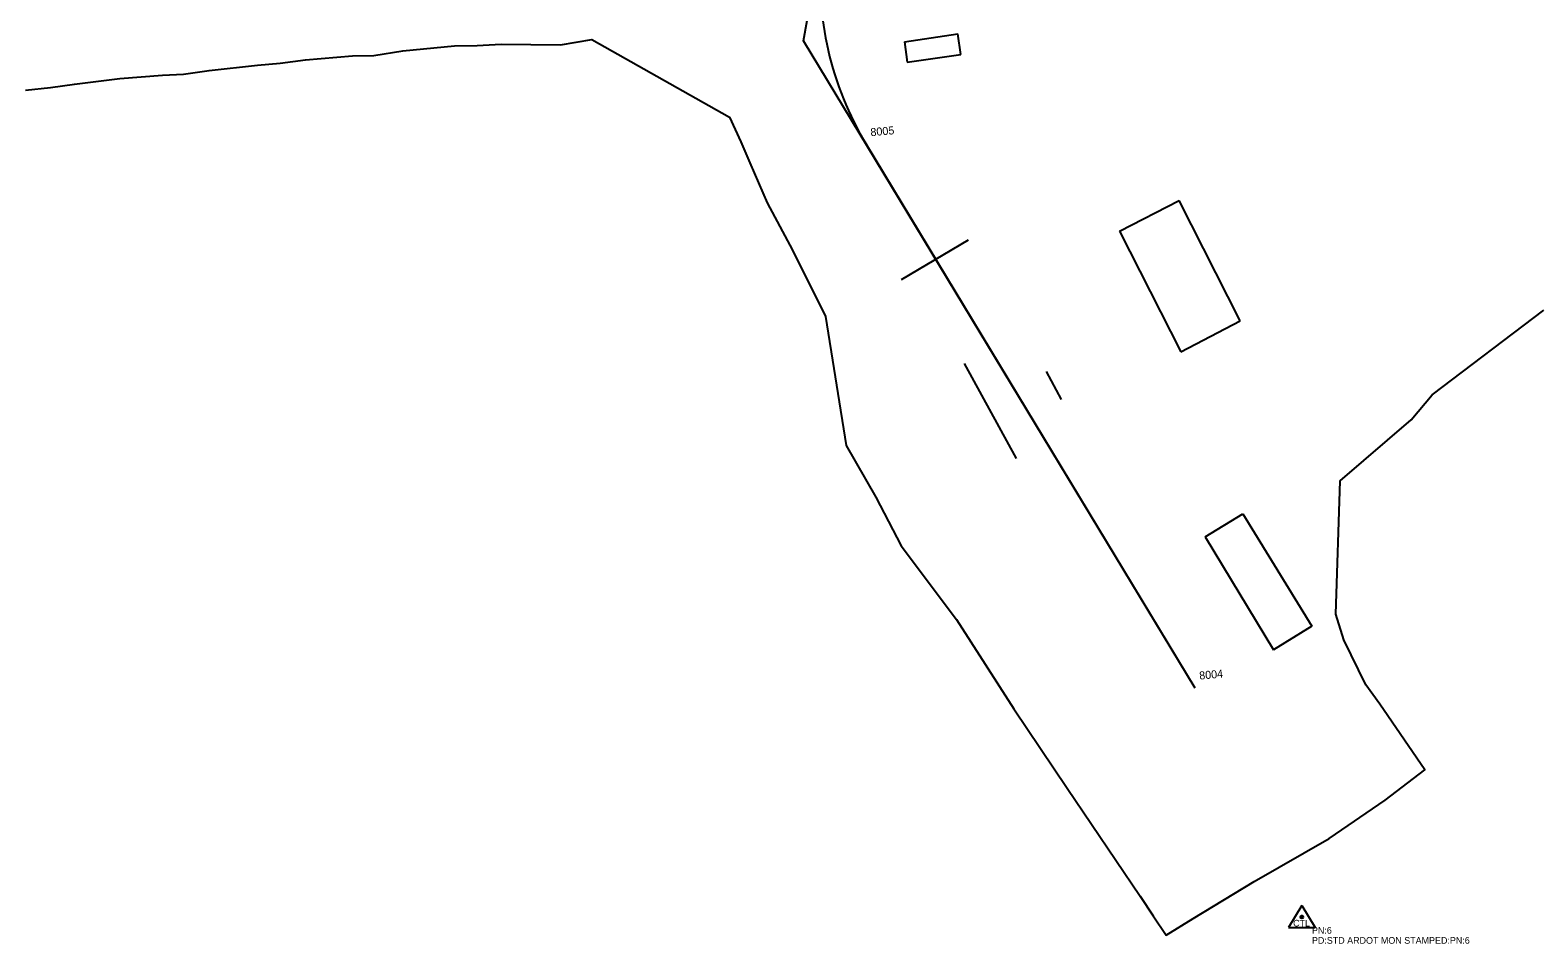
# Model space of a CAD drawing. Extents: x 1734463 to 1738841, y 377458 to 380217.
# Drawn here: x 1735592 to 1736720, y 377458 to 378142 of the extents above; entities that cross this region are included whole.
import ezdxf

# ---------------------------------------------------------------- set-up
doc = ezdxf.new("R2010")
doc.units = 0
doc.layers.add('R_Horz Alg Stationing', color=7, linetype='Continuous')
doc.layers.add('S_PRIMARY_CTL_ANNOT', color=7, linetype='Continuous')

msp = doc.modelspace()

# ---------------------------------------------------------------- linework, layer by layer
for p, q in [((1736170.6, 378134.3), (1736210.9, 378361.2)), ((1736463.7, 377649.8), (1736170.6, 378134.3)), ((1736246.2, 378133.5), (1736286.1, 378139.4)), ((1736246.2, 378133.5), (1736286.1, 378139.4)), ((1736246.2, 378133.5), (1736248.3, 378118.3)), ((1736246.2, 378133.5), (1736248.3, 378118.3)), ((1736288.3, 378124), (1736286.1, 378139.4)), ((1736288.3, 378124), (1736286.1, 378139.4)), ((1736248.3, 378118.3), (1736288.3, 378124)), ((1736248.3, 378118.3), (1736288.3, 378124)), ((1736463.7, 377649.8), (1736217.7, 378056.5)), ((1736407.1, 377991.8), (1736451.9, 378014.7)), ((1736407.1, 377991.8), (1736451.9, 378014.7)), ((1736497.6, 377924.7), (1736451.9, 378014.7)), ((1736497.6, 377924.7), (1736451.9, 378014.7)), ((1736407.1, 377991.8), (1736453, 377901.5)), ((1736407.1, 377991.8), (1736453, 377901.5)), ((1736243.9, 377955.6), (1736294.1, 377985.3)), ((1736243.9, 377955.6), (1736294.1, 377985.3)), ((1736453, 377901.5), (1736497.6, 377924.7)), ((1736453, 377901.5), (1736497.6, 377924.7)), ((1736291, 377892.8), (1736329.8, 377821.7)), ((1736291, 377892.8), (1736329.8, 377821.7)), ((1736363.8, 377865.7), (1736352.6, 377886.7)), ((1736363.8, 377865.7), (1736352.6, 377886.7)), ((1736471.2, 377762.9), (1736499.4, 377780.2)), ((1736471.2, 377762.9), (1736499.4, 377780.2)), ((1736499.4, 377780.2), (1736551.2, 377696.1)), ((1736499.4, 377780.2), (1736551.2, 377696.1)), ((1736471.2, 377762.9), (1736522.5, 377678.3)), ((1736471.2, 377762.9), (1736522.5, 377678.3)), ((1736551.2, 377696.1), (1736522.5, 377678.3)), ((1736551.2, 377696.1), (1736522.5, 377678.3))]:
    msp.add_line(p, q)
msp.add_lwpolyline([(1735588.3, 378097.3), (1735607, 378099.4), (1735624.8, 378101.8), (1735658.8, 378105.9), (1735690.8, 378108.4), (1735706.6, 378109.2), (1735725.8, 378111.9), (1735762, 378116), (1735778.8, 378117.5), (1735797.9, 378120), (1735833, 378122.9), (1735849, 378123.2), (1735870.7, 378126.7), (1735909.4, 378130.4), (1735926.3, 378130.6), (1735944.2, 378131.7), (1735988.6, 378131.2), (1736012.1, 378135.2), (1736115.2, 378077.1), (1736123.6, 378058.5), (1736130.4, 378042.9), (1736136.9, 378027.9), (1736143.4, 378012.9), (1736152.9, 377995.3), (1736162.4, 377977.6), (1736187, 377927.9), (1736202.6, 377831.4), (1736224.7, 377792.6), (1736234.2, 377774.5), (1736243.6, 377756.3), (1736285.1, 377701.2), (1736328.1, 377634.3), (1736367.9, 377574.9), (1736422.5, 377494), (1736432.3, 377479.4), (1736442.2, 377464.9), (1736462.2, 377477.3), (1736507.9, 377505), (1736564, 377537.2), (1736606.1, 377565.8), (1736635.6, 377588.5), (1736602, 377637.8), (1736591.6, 377652.2), (1736575.2, 377685.9), (1736569, 377705.2), (1736572.3, 377805), (1736625.5, 377850.6), (1736641.3, 377869.2), (1736724.7, 377932.5)])
msp.add_arc((1736424.1, 378181.4), 241.2, 174.7889, 211.1667)
at = {"layer": 'S_PRIMARY_CTL_ANNOT'}
for p, q in [((1736543.7, 377487.1), (1736533.7, 377470.6)), ((1736543.7, 377487.1), (1736553.5, 377470.6)), ((1736533.7, 377470.6), (1736553.5, 377470.6))]:
    msp.add_line(p, q, dxfattribs=at)
for radius in [1.04, 0.609, 0.344]:
    msp.add_circle((1736543.7, 377478.4), radius, dxfattribs=at)

# ---------------------------------------------------------------- texts
at = {"layer": 'R_Horz Alg Stationing'}
for s, p in [('8005', (1736221, 378062.8)), ('8004', (1736467.1, 377656.1))]:
    msp.add_text(s, height=6, rotation=5, dxfattribs=at).set_placement(p)
at = {"layer": 'S_PRIMARY_CTL_ANNOT'}
for s, p in [('CTL', (1736537.1, 377471.3)), ('PN:6', (1736551.2, 377465.9)), ('PD:STD ARDOT MON STAMPED:PN:6', (1736551.2, 377458.4))]:
    msp.add_text(s, height=5, dxfattribs=at).set_placement(p)

doc.saveas('drawing.dxf')
